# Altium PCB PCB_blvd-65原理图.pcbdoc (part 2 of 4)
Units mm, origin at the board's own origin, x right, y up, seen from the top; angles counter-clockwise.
Board outline 317.5 x 107.96 mm, 2 copper layers (Top Layer, Bottom Layer); 180 components, 111 nets, 404 pads, 231 vias.
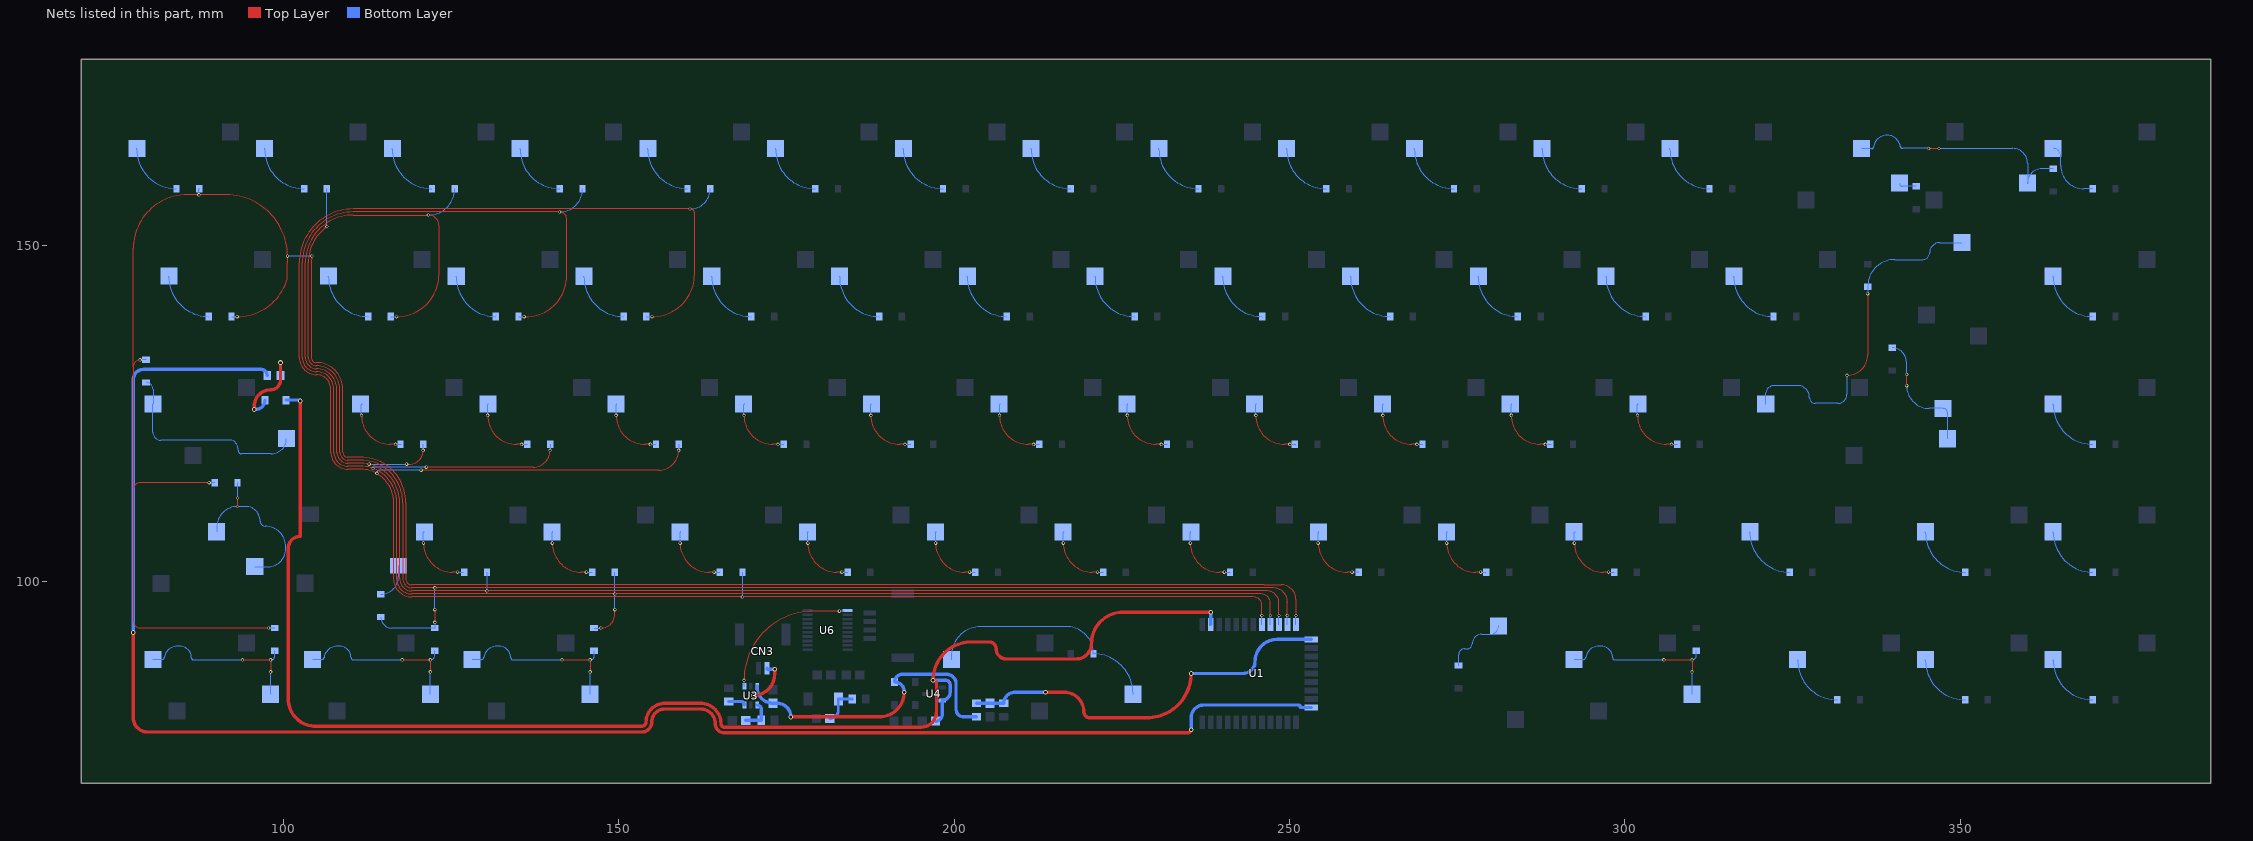
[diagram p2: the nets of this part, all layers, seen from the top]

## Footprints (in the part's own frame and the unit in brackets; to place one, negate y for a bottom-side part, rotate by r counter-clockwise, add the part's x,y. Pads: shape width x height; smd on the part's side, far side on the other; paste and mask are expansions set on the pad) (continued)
凯华轴座无灯#2 [mm]
  rect 2.54x2.54 smd far side: COL(-7.6,2.59)
  rect 2.54x2.3 smd far side: ROW(6.35,5.2)
  Multi-Layer board cut-out: -2.285,2.565 -2.49,3.31 -3.038,3.854 -3.785,4.053 -4.531,3.854 -5.079,3.31 -5.284,2.565 -5.284,2.565 -5.079,1.821 -4.531,1.277 -3.785,1.078 -3.038,1.277 -2.49,1.821 -2.285,2.565
  Multi-Layer board cut-out: 4.116,4.953 3.911,5.698 3.363,6.242 2.616,6.441 1.87,6.242 1.321,5.698 1.116,4.953 1.116,4.953 1.321,4.208 1.87,3.664 2.616,3.465 3.363,3.664 3.911,4.208 4.116,4.953
  Multi-Layer board cut-out: 2,0 1.802,0.868 1.247,1.564 0.445,1.95 -0.445,1.95 -1.247,1.564 -1.802,0.868 -2,0 -2,0 -1.802,-0.868 -1.247,-1.564 -0.445,-1.95 0.445,-1.95 1.247,-1.564 1.802,-0.868 2,0
  Multi-Layer board cut-out: -4.028,-0.025 -4.157,0.448 -4.505,0.793 -4.978,0.92 -5.452,0.793 -5.799,0.448 -5.928,-0.025 -5.928,-0.025 -5.799,-0.498 -5.452,-0.844 -4.978,-0.97 -4.505,-0.844 -4.157,-0.498 -4.028,-0.025
  Multi-Layer board cut-out: 5.979,-0.025 5.85,0.448 5.503,0.793 5.029,0.92 4.556,0.793 4.208,0.448 4.079,-0.025 4.079,-0.025 4.208,-0.498 4.556,-0.844 5.029,-0.97 5.503,-0.844 5.85,-0.498 5.979,-0.025
  Multi-Layer keep-out region: -2.285,2.565 -2.49,3.31 -3.038,3.854 -3.785,4.053 -4.531,3.854 -5.079,3.31 -5.284,2.565 -5.284,2.565 -5.079,1.821 -4.531,1.277 -3.785,1.078 -3.038,1.277 -2.49,1.821 -2.285,2.565
  Multi-Layer keep-out region: 4.116,4.953 3.911,5.698 3.363,6.242 2.616,6.441 1.87,6.242 1.321,5.698 1.116,4.953 1.116,4.953 1.321,4.208 1.87,3.664 2.616,3.465 3.363,3.664 3.911,4.208 4.116,4.953
  Multi-Layer keep-out region: 2,0 1.802,0.868 1.247,1.564 0.445,1.95 -0.445,1.95 -1.247,1.564 -1.802,0.868 -2,0 -2,0 -1.802,-0.868 -1.247,-1.564 -0.445,-1.95 0.445,-1.95 1.247,-1.564 1.802,-0.868 2,0
  Multi-Layer keep-out region: -4.028,-0.025 -4.157,0.448 -4.505,0.793 -4.978,0.92 -5.452,0.793 -5.799,0.448 -5.928,-0.025 -5.928,-0.025 -5.799,-0.498 -5.452,-0.844 -4.978,-0.97 -4.505,-0.844 -4.157,-0.498 -4.028,-0.025
  Multi-Layer keep-out region: 5.979,-0.025 5.85,0.448 5.503,0.793 5.029,0.92 4.556,0.793 4.208,0.448 4.079,-0.025 4.079,-0.025 4.208,-0.498 4.556,-0.844 5.029,-0.97 5.503,-0.844 5.85,-0.498 5.979,-0.025
凯华轴座无灯#3 [mm]
  rect 2.54x2.3 smd far side: COL(-7.6,2.47)
  rect 2.54x2.54 smd far side: ROW(6.35,5.08)
  Multi-Layer board cut-out: -5.285,2.565 -5.079,1.821 -4.531,1.278 -3.785,1.079 -3.039,1.278 -2.49,1.821 -2.285,2.565 -2.285,2.565 -2.49,3.309 -3.039,3.853 -3.785,4.052 -4.531,3.853 -5.079,3.31 -5.285,2.565
  Multi-Layer board cut-out: 1.116,4.953 1.322,4.209 1.87,3.665 2.616,3.467 3.362,3.665 3.911,4.209 4.116,4.953 4.116,4.953 3.911,5.697 3.362,6.24 2.616,6.439 1.87,6.241 1.322,5.697 1.116,4.953
  Multi-Layer board cut-out: -2,0 -1.802,-0.868 -1.247,-1.564 -0.445,-1.95 0.445,-1.95 1.247,-1.564 1.802,-0.868 2,0 2,0 1.732,1 1,1.732 0,2 -1,1.732 -1.732,1 -2,0
  Multi-Layer board cut-out: -5.928,-0.025 -5.799,-0.497 -5.451,-0.842 -4.978,-0.969 -4.505,-0.842 -4.158,-0.498 -4.028,-0.026 -4.028,-0.026 -4.158,0.447 -4.505,0.791 -4.978,0.918 -5.451,0.792 -5.799,0.447 -5.928,-0.025
  Multi-Layer board cut-out: 4.079,-0.025 4.209,-0.497 4.556,-0.842 5.029,-0.969 5.502,-0.842 5.85,-0.498 5.979,-0.026 5.979,-0.026 5.85,0.447 5.502,0.791 5.029,0.918 4.556,0.792 4.209,0.447 4.079,-0.025
  Multi-Layer keep-out region: -5.285,2.565 -5.079,1.821 -4.531,1.278 -3.785,1.079 -3.039,1.278 -2.49,1.821 -2.285,2.565 -2.285,2.565 -2.49,3.309 -3.039,3.853 -3.785,4.052 -4.531,3.853 -5.079,3.31 -5.285,2.565
  Multi-Layer keep-out region: 1.116,4.953 1.322,4.209 1.87,3.665 2.616,3.467 3.362,3.665 3.911,4.209 4.116,4.953 4.116,4.953 3.911,5.697 3.362,6.24 2.616,6.439 1.87,6.241 1.322,5.697 1.116,4.953
  Multi-Layer keep-out region: -2,0 -1.802,-0.868 -1.247,-1.564 -0.445,-1.95 0.445,-1.95 1.247,-1.564 1.802,-0.868 2,0 2,0 1.732,1 1,1.732 0,2 -1,1.732 -1.732,1 -2,0
  Multi-Layer keep-out region: -5.928,-0.025 -5.799,-0.497 -5.451,-0.842 -4.978,-0.969 -4.505,-0.842 -4.158,-0.498 -4.028,-0.026 -4.028,-0.026 -4.158,0.447 -4.505,0.791 -4.978,0.918 -5.451,0.792 -5.799,0.447 -5.928,-0.025
  Multi-Layer keep-out region: 4.079,-0.025 4.209,-0.497 4.556,-0.842 5.029,-0.969 5.502,-0.842 5.85,-0.498 5.979,-0.026 5.979,-0.026 5.85,0.447 5.502,0.791 5.029,0.918 4.556,0.792 4.209,0.447 4.079,-0.025
凯华轴座无灯#4 [mm]
  rect 2.54x2.54 smd far side: COL(-7.6,2.59) ROW(6.35,5.08)
  Multi-Layer board cut-out: -3.785,4.065 -4.435,3.917 -4.957,3.501 -5.247,2.899 -5.247,2.232 -4.957,1.63 -4.435,1.214 -3.785,1.065 -3.785,1.065 -3.134,1.214 -2.612,1.63 -2.322,2.232 -2.322,2.899 -2.612,3.501 -3.134,3.917 -3.785,4.065
  Multi-Layer board cut-out: 2.616,6.453 1.965,6.304 1.443,5.888 1.154,5.287 1.154,4.619 1.443,4.018 1.965,3.602 2.616,3.453 2.616,3.453 3.267,3.602 3.789,4.018 4.079,4.619 4.079,5.287 3.789,5.888 3.267,6.304 2.616,6.453
  Multi-Layer board cut-out: 0,2 -0.993,1.727 -1.719,0.995 -1.984,0 -1.719,-0.995 -0.993,-1.727 0,-2 0,-2 0.993,-1.727 1.719,-0.995 1.984,0 1.719,0.995 0.993,1.727 0,2
  Multi-Layer board cut-out: -4.978,0.925 -5.391,0.831 -5.721,0.567 -5.905,0.186 -5.905,-0.237 -5.721,-0.618 -5.391,-0.881 -4.978,-0.975 -4.978,-0.975 -4.503,-0.848 -4.156,-0.5 -4.028,-0.025 -4.156,0.45 -4.503,0.797 -4.978,0.925
  Multi-Layer board cut-out: 5.029,0.925 4.617,0.831 4.286,0.567 4.103,0.186 4.103,-0.237 4.286,-0.618 4.617,-0.881 5.029,-0.975 5.029,-0.975 5.504,-0.848 5.852,-0.5 5.979,-0.025 5.852,0.45 5.504,0.797 5.029,0.925
  Multi-Layer keep-out region: -3.785,4.065 -4.435,3.917 -4.957,3.501 -5.247,2.899 -5.247,2.232 -4.957,1.63 -4.435,1.214 -3.785,1.065 -3.785,1.065 -3.134,1.214 -2.612,1.63 -2.322,2.232 -2.322,2.899 -2.612,3.501 -3.134,3.917 -3.785,4.065
  Multi-Layer keep-out region: 2.616,6.453 1.965,6.304 1.443,5.888 1.154,5.287 1.154,4.619 1.443,4.018 1.965,3.602 2.616,3.453 2.616,3.453 3.267,3.602 3.789,4.018 4.079,4.619 4.079,5.287 3.789,5.888 3.267,6.304 2.616,6.453
  Multi-Layer keep-out region: 0,2 -0.993,1.727 -1.719,0.995 -1.984,0 -1.719,-0.995 -0.993,-1.727 0,-2 0,-2 0.993,-1.727 1.719,-0.995 1.984,0 1.719,0.995 0.993,1.727 0,2
  Multi-Layer keep-out region: -4.978,0.925 -5.391,0.831 -5.721,0.567 -5.905,0.186 -5.905,-0.237 -5.721,-0.618 -5.391,-0.881 -4.978,-0.975 -4.978,-0.975 -4.503,-0.848 -4.156,-0.5 -4.028,-0.025 -4.156,0.45 -4.503,0.797 -4.978,0.925
  Multi-Layer keep-out region: 5.029,0.925 4.617,0.831 4.286,0.567 4.103,0.186 4.103,-0.237 4.286,-0.618 4.617,-0.881 5.029,-0.975 5.029,-0.975 5.504,-0.848 5.852,-0.5 5.979,-0.025 5.852,0.45 5.504,0.797 5.029,0.925
卫星轴2U#1 [mm]
  Multi-Layer board cut-out: -9.987,7.703 -10.203,8.485 -10.779,9.055 -11.562,9.264 -12.346,9.055 -12.922,8.485 -13.137,7.703 -13.137,7.703 -12.922,6.922 -12.346,6.351 -11.562,6.142 -10.779,6.351 -10.203,6.922 -9.987,7.703
  Multi-Layer board cut-out: 13.812,7.703 13.597,8.485 13.021,9.055 12.237,9.264 11.454,9.055 10.878,8.485 10.662,7.703 10.662,7.703 10.878,6.922 11.454,6.351 12.237,6.142 13.021,6.351 13.597,6.922 13.812,7.703
  Multi-Layer board cut-out: -9.562,-7.636 -9.761,-6.768 -10.315,-6.072 -11.117,-5.686 -12.008,-5.686 -12.809,-6.072 -13.364,-6.768 -13.563,-7.636 -13.563,-7.636 -13.364,-8.504 -12.809,-9.2 -12.008,-9.586 -11.117,-9.586 -10.315,-9.2 -9.76,-8.504 -9.562,-7.636
  Multi-Layer board cut-out: 14.237,-7.636 14.039,-6.768 13.484,-6.072 12.682,-5.686 11.792,-5.686 10.99,-6.072 10.435,-6.768 10.237,-7.636 10.237,-7.636 10.435,-8.504 10.99,-9.2 11.792,-9.586 12.682,-9.586 13.484,-9.2 14.039,-8.504 14.237,-7.636
  Multi-Layer keep-out region: -9.987,7.703 -10.203,8.485 -10.779,9.055 -11.562,9.264 -12.346,9.055 -12.922,8.485 -13.137,7.703 -13.137,7.703 -12.922,6.922 -12.346,6.351 -11.562,6.142 -10.779,6.351 -10.203,6.922 -9.987,7.703
  Multi-Layer keep-out region: 13.812,7.703 13.597,8.485 13.021,9.055 12.237,9.264 11.454,9.055 10.878,8.485 10.662,7.703 10.662,7.703 10.878,6.922 11.454,6.351 12.237,6.142 13.021,6.351 13.597,6.922 13.812,7.703
  Multi-Layer keep-out region: -9.562,-7.636 -9.761,-6.768 -10.315,-6.072 -11.117,-5.686 -12.008,-5.686 -12.809,-6.072 -13.364,-6.768 -13.563,-7.636 -13.563,-7.636 -13.364,-8.504 -12.809,-9.2 -12.008,-9.586 -11.117,-9.586 -10.315,-9.2 -9.76,-8.504 -9.562,-7.636
  Multi-Layer keep-out region: 14.237,-7.636 14.039,-6.768 13.484,-6.072 12.682,-5.686 11.792,-5.686 10.99,-6.072 10.435,-6.768 10.237,-7.636 10.237,-7.636 10.435,-8.504 10.99,-9.2 11.792,-9.586 12.682,-9.586 13.484,-9.2 14.039,-8.504 14.237,-7.636
卫星轴2U#2 [mm]
  Multi-Layer board cut-out: -11.562,9.278 -12.246,9.122 -12.794,8.685 -13.098,8.054 -13.098,7.353 -12.794,6.721 -12.246,6.284 -11.562,6.128 -11.562,6.128 -10.879,6.284 -10.331,6.721 -10.027,7.353 -10.027,8.054 -10.331,8.685 -10.879,9.122 -11.562,9.278
  Multi-Layer board cut-out: 12.237,9.278 11.554,9.122 11.006,8.685 10.702,8.054 10.702,7.353 11.006,6.721 11.554,6.284 12.237,6.128 12.237,6.128 12.921,6.284 13.469,6.721 13.773,7.353 13.773,8.054 13.469,8.685 12.921,9.122 12.237,9.278
  Multi-Layer board cut-out: -11.562,-5.636 -12.558,-5.907 -13.286,-6.639 -13.552,-7.636 -13.286,-8.633 -12.558,-9.365 -11.562,-9.636 -11.562,-9.636 -10.567,-9.365 -9.839,-8.633 -9.572,-7.636 -9.839,-6.639 -10.567,-5.907 -11.562,-5.636
  Multi-Layer board cut-out: 12.237,-5.636 11.242,-5.907 10.514,-6.639 10.247,-7.636 10.514,-8.633 11.242,-9.365 12.237,-9.636 12.237,-9.636 13.233,-9.365 13.961,-8.633 14.227,-7.636 13.961,-6.639 13.233,-5.907 12.237,-5.636
  Multi-Layer keep-out region: -11.562,9.278 -12.246,9.122 -12.794,8.685 -13.098,8.054 -13.098,7.353 -12.794,6.721 -12.246,6.284 -11.562,6.128 -11.562,6.128 -10.879,6.284 -10.331,6.721 -10.027,7.353 -10.027,8.054 -10.331,8.685 -10.879,9.122 -11.562,9.278
  Multi-Layer keep-out region: 12.237,9.278 11.554,9.122 11.006,8.685 10.702,8.054 10.702,7.353 11.006,6.721 11.554,6.284 12.237,6.128 12.237,6.128 12.921,6.284 13.469,6.721 13.773,7.353 13.773,8.054 13.469,8.685 12.921,9.122 12.237,9.278
  Multi-Layer keep-out region: -11.562,-5.636 -12.558,-5.907 -13.286,-6.639 -13.552,-7.636 -13.286,-8.633 -12.558,-9.365 -11.562,-9.636 -11.562,-9.636 -10.567,-9.365 -9.839,-8.633 -9.572,-7.636 -9.839,-6.639 -10.567,-5.907 -11.562,-5.636
  Multi-Layer keep-out region: 12.237,-5.636 11.242,-5.907 10.514,-6.639 10.247,-7.636 10.514,-8.633 11.242,-9.365 12.237,-9.636 12.237,-9.636 13.233,-9.365 13.961,-8.633 14.227,-7.636 13.961,-6.639 13.233,-5.907 12.237,-5.636

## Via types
v1: diameter 0.5, hole 0.3, Top Layer to Bottom Layer, 198 vias
v2: diameter 0.7, hole 0.4, Top Layer to Bottom Layer, 33 vias

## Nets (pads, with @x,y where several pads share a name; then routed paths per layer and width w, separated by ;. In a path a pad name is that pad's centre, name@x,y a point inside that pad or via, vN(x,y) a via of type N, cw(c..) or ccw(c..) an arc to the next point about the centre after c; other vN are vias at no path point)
3V3: C10.2 LED1.1 U1.2 U4.2 | length 218.4
  Top Layer w0.5: v2(102.489,126.873) 102.489,106.68 ccw(c102.489,104.902) 100.711,104.902 100.711,82.423 ccw(c104.775,82.423) 104.775,78.359 153.416,78.359 ccw(c153.416,78.994) 154.051,78.994 cw(c156.845,78.994) 156.845,81.788 162.179,81.788 cw(c162.179,78.74) 165.227,78.74 ccw(c165.735,78.74) 165.735,78.232 195.072,78.232 ccw(c195.072,80.518) 197.358,80.518 197.358,84.709 ccw(c196.85,84.709) v2(196.85,85.217) cw(c202.565,85.217) 202.565,90.932 205.232,90.932 cw(c205.232,89.916) 206.248,89.916 ccw(c207.772,89.916) 207.772,88.392 218.186,88.392 ccw(c218.186,90.678) 220.472,90.678 cw(c225.171,90.678) 225.171,95.377 v2(238.252,95.377)
  Bottom Layer w0.5: LED1.1@100.386,127 102.362,127 cw(c102.362,126.873) v2(102.489,126.873) ; v2(196.85,85.217) 198.755,85.217 cw(c198.755,84.582) 199.39,84.582 199.39,83.413 cw(c198.212,83.413) U4.2@198.212,82.235 198.212,80.118 cw(c197.215,80.118) C10.2@197.215,79.121 ; v2(238.252,95.377) 238.252,93.544 ccw(c238.263,93.544) U1.2@238.263,93.533
$1N338: C6.2 R1.1 U3.4 | length 4.9
  Bottom Layer w0.5: C6.2@168.894,79.248 R1.1@171.212,79.248 171.212,80.941 ccw(c170.622,80.941) U3.4@170.622,81.531
$1N367: R2.1 U3.6 | length 2.7
  Bottom Layer w0.5: R2.1@166.37,82.058 168.195,82.058 cw(c168.195,81.531) U3.6@168.722,81.531
$1N421: C1.2 R5.2 SW2.1 | length 5.7
  Bottom Layer w0.4: C1.2@181.467,79.502 ccw(c181.467,80.752) 182.717,80.752 SW2.1@182.717,82.423 R5.2@184.801,82.423
$1N505: D10.1 KEY00.COL | length 9.4
  Bottom Layer w0.1: KEY00.COL@78.125,164.516 78.125,164.404 ccw(c84.033,164.404) D10.1@84.033,158.496
$1N744: LED1.2 R8.1 | length 13.5
  Top Layer w0.5: v2(95.631,125.603) 95.631,126.111 cw(c98.044,126.111) 98.044,128.524 ccw(c98.044,130.032) 99.552,130.032 v2(99.552,132.588)
  Bottom Layer w0.5: v2(95.631,125.603) 95.829,125.603 ccw(c95.829,127) LED1.2@97.226,127 ; R8.1@99.552,130.683 v2(99.552,132.588)
$1N1103: D1.1 KEY01.COL | length 9.4
  Bottom Layer w0.1: KEY01.COL@97.175,164.516 97.175,164.404 ccw(c103.083,164.404) D1.1@103.083,158.496
$1N1104: D2.1 KEY02.COL | length 9.4
  Bottom Layer w0.1: KEY02.COL@116.225,164.516 116.225,164.404 ccw(c122.133,164.404) D2.1@122.133,158.496
$1N1105: D3.1 KEY03.COL | length 9.4
  Bottom Layer w0.1: KEY03.COL@135.275,164.516 135.275,164.404 ccw(c141.183,164.404) D3.1@141.183,158.496
$1N1106: D4.1 KEY04.COL | length 9.4
  Bottom Layer w0.1: KEY04.COL@154.325,164.516 154.325,164.404 ccw(c160.233,164.404) D4.1@160.233,158.496
$1N1107: D5.1 KEY05.COL | length 9.4
  Bottom Layer w0.1: KEY05.COL@173.374,164.516 173.374,164.405 ccw(c179.283,164.405) D5.1@179.283,158.496
$1N1108: D6.1 KEY06.COL | length 9.4
  Bottom Layer w0.1: KEY06.COL@192.423,164.516 192.423,164.406 ccw(c198.333,164.406) D6.1@198.333,158.496
$1N1109: D7.1 KEY07.COL | length 9.4
  Bottom Layer w0.1: KEY07.COL@211.475,164.516 211.475,164.404 ccw(c217.383,164.404) D7.1@217.383,158.496
$1N1110: D8.1 KEY08.COL | length 9.4
  Bottom Layer w0.1: KEY08.COL@230.525,164.516 230.525,164.404 ccw(c236.433,164.404) D8.1@236.433,158.496
$1N1111: D9.1 KEY09.COL | length 9.4
  Bottom Layer w0.1: KEY09.COL@249.575,164.516 249.575,164.404 ccw(c255.483,164.404) D9.1@255.483,158.496
$1N1112: D11.1 KEY010.COL | length 9.4
  Bottom Layer w0.1: KEY010.COL@268.626,164.515 268.626,164.403 ccw(c274.533,164.403) D11.1@274.533,158.496
$1N1113: D12.1 KEY011.COL | length 9.4
  Bottom Layer w0.1: KEY011.COL@287.675,164.516 287.675,164.404 ccw(c293.583,164.404) D12.1@293.583,158.496
$1N1114: D13.1 KEY012.COL | length 9.4
  Bottom Layer w0.1: KEY012.COL@306.726,164.515 306.726,164.403 ccw(c312.633,164.403) D13.1@312.633,158.496
$1N1115: D14.1 KEY013.COL | length 2.8
  Bottom Layer w0.1: KEY013.COL@340.975,159.335 ccw(c341.454,159.335) 341.454,158.857 D14.1@343.463,158.857
$1N1116: D15.1 KEY014.COL KEY014_CP.COL | length 36.3
  Top Layer w0.1: v1(345.313,164.515) v1(346.837,164.515)
  Bottom Layer w0.1: KEY014_CP.COL@335.3,164.52 ccw(c335.355,164.52) 335.355,164.465 336.843,164.465 ccw(c336.843,164.694) 337.066,164.643 ; v1(345.313,164.515) 341.41,164.515 cw(c341.41,164.837) 341.104,164.736 ; v1(346.837,164.515) 357.836,164.515 cw(c357.836,162.306) 360.045,162.306 KEY014.COL@360.045,159.636 ; D15.1@363.874,161.483 362.168,161.483 ccw(c362.168,159.34) KEY014.COL@360.045,159.636 ; 337.066,164.643 ccw(c336.843,164.694) 337.072,164.694 337.072,164.7 ; 337.066,164.643 cw(c339.09,164.465) 337.072,164.7 ; 337.072,164.7 cw(c339.09,164.465) 339.09,166.497 cw(c339.09,164.465) 341.088,164.837 ; 341.088,164.837 ccw(c341.41,164.837) 341.104,164.736 ; 341.088,164.837 cw(c339.09,164.465) 341.104,164.736 ; KEY014.COL@360.045,159.636 360.045,159.361 cw(c360.025,159.361) KEY014.COL@360.025,159.34 cw(c362.168,159.34) KEY014.COL@360.045,159.636
$1N1117: D16.1 KEY015.COL | length 10
  Bottom Layer w0.1: KEY015.COL@363.875,164.516 cw(c363.875,163.393) 364.998,163.393 364.998,161.925 ccw(c368.427,161.925) 368.427,158.496 D16.1@369.783,158.496
$1N1577: D17.1 KEY115.COL | length 9.4
  Bottom Layer w0.1: KEY115.COL@363.876,145.465 363.876,145.353 ccw(c369.783,145.353) D17.1@369.783,139.446
$1N1578: D18.1 KEY114.COL KEY114_CP.COL | length 52.3
  Top Layer w0.1: v1(333.121,130.683) 333.159,130.683 ccw(c333.159,133.731) 336.207,133.731 v1(336.207,142.875)
  Bottom Layer w0.1: KEY114_CP.COL@321.013,126.415 cw(c321.013,126.498) 320.929,126.498 320.929,127.762 cw(c322.326,127.762) 322.326,129.159 325.755,129.159 cw(c325.755,127.381) 327.533,127.381 ccw(c328.422,127.381) 328.422,126.492 331.724,126.492 ccw(c331.724,127.889) 333.121,127.889 v1(333.121,130.683) ; v1(336.207,142.875) D18.1@336.207,143.881 cw(c340.281,143.881) 340.281,147.955 344.424,147.955 ccw(c344.424,148.971) 345.44,148.971 cw(c346.941,148.971) 346.941,150.472 KEY114.COL@350.255,150.472
$1N1579: D19.1 KEY113.COL | length 9.4
  Bottom Layer w0.1: KEY113.COL@316.251,145.465 316.251,145.354 ccw(c322.158,145.354) D19.1@322.158,139.446
$1N1580: D20.1 KEY112.COL | length 9.4
  Bottom Layer w0.1: KEY112.COL@297.201,145.465 297.201,145.353 ccw(c303.108,145.353) D20.1@303.108,139.446
$1N1581: D21.1 KEY111.COL | length 9.4
  Bottom Layer w0.1: KEY111.COL@278.151,145.465 278.151,145.353 ccw(c284.058,145.353) D21.1@284.058,139.446
$1N1582: D22.1 KEY110.COL | length 9.4
  Bottom Layer w0.1: KEY110.COL@259.101,145.465 259.101,145.354 ccw(c265.008,145.354) D22.1@265.008,139.446
$1N1583: D23.1 KEY19.COL | length 9.4
  Bottom Layer w0.1: KEY19.COL@240.05,145.465 240.05,145.354 ccw(c245.958,145.354) D23.1@245.958,139.446
$1N1584: D24.1 KEY18.COL | length 9.4
  Bottom Layer w0.1: KEY18.COL@221.001,145.465 221.001,145.353 ccw(c226.908,145.353) D24.1@226.908,139.446
$1N1585: D25.1 KEY17.COL | length 9.4
  Bottom Layer w0.1: KEY17.COL@201.951,145.465 201.951,145.353 ccw(c207.858,145.353) D25.1@207.858,139.446
$1N1586: D26.1 KEY16.COL | length 9.4
  Bottom Layer w0.1: KEY16.COL@182.901,145.465 182.901,145.353 ccw(c188.808,145.353) D26.1@188.808,139.446
$1N1587: D27.1 KEY15.COL | length 9.4
  Bottom Layer w0.1: KEY15.COL@163.851,145.465 163.851,145.354 ccw(c169.758,145.354) D27.1@169.758,139.446
$1N1588: D28.1 KEY14.COL | length 9.4
  Bottom Layer w0.1: KEY14.COL@144.8,145.465 144.8,145.354 ccw(c150.708,145.354) D28.1@150.708,139.446
$1N1589: D29.1 KEY13.COL | length 9.4
  Bottom Layer w0.1: KEY13.COL@125.751,145.465 125.751,145.354 ccw(c131.658,145.354) D29.1@131.658,139.446
$1N1590: D30.1 KEY12.COL | length 9.4
  Bottom Layer w0.1: KEY12.COL@106.7,145.466 106.7,145.354 ccw(c112.608,145.354) D30.1@112.608,139.446
$1N1891: D32.1 KEY10.COL | length 9.4
  Bottom Layer w0.1: KEY10.COL@82.888,145.466 82.888,145.417 ccw(c88.859,145.417) D32.1@88.859,139.446
$1N2119: D33.1 KEY215.COL | length 9.4
  Bottom Layer w0.1: KEY215.COL@363.876,126.415 363.876,126.303 ccw(c369.783,126.303) D33.1@369.783,120.396
$1N2120: D35.1 KEY213.COL KEY213_CP.COL | length 19.1
  Top Layer w0.1: v1(342.011,129.159) v1(342.011,130.81)
  Bottom Layer w0.1: D35.1@339.852,134.789 cw(c339.852,132.63) 342.011,132.63 v1(342.011,130.81) ; v1(342.011,129.159) ccw(c345.423,129.159) 345.423,125.748 KEY213_CP.COL@347.454,125.748 cw(c347.454,125.083) 348.119,125.083 KEY213.COL@348.119,121.232
$1N2121: D36.1 KEY212.COL | length 10.1
  Top Layer w0.1: v1(301.879,124.714) ccw(c306.197,124.714) 306.197,120.396 v1(306.959,120.396)
  Bottom Layer w0.1: v1(301.879,124.714) 301.879,126.321 cw(c301.963,126.321) KEY212.COL@301.963,126.405 ; v1(306.959,120.396) D36.1@307.807,120.396
$1N2122: D37.1 KEY211.COL | length 10.1
  Top Layer w0.1: v1(283.073,124.714) ccw(c287.391,124.714) 287.391,120.396 v1(288.153,120.396)
  Bottom Layer w0.1: v1(283.073,124.714) 283.073,126.321 cw(c283.157,126.321) KEY211.COL@283.157,126.405 ; v1(288.153,120.396) D37.1@289.001,120.396
$1N2123: D38.1 KEY210.COL | length 10.1
  Top Layer w0.1: v1(263.906,124.714) ccw(c268.224,124.714) 268.224,120.396 v1(268.986,120.396)
  Bottom Layer w0.1: v1(263.906,124.714) 263.906,126.321 cw(c263.99,126.321) KEY210.COL@263.99,126.405 ; v1(268.986,120.396) D38.1@269.834,120.396
$1N2124: D39.1 KEY29.COL | length 10.1
  Top Layer w0.1: v1(244.973,124.714) ccw(c249.291,124.714) 249.291,120.396 v1(250.053,120.396)
  Bottom Layer w0.1: v1(244.973,124.714) 244.973,126.321 cw(c245.057,126.321) KEY29.COL@245.057,126.405 ; v1(250.053,120.396) D39.1@250.901,120.396
$1N2125: D40.1 KEY28.COL | length 10.1
  Top Layer w0.1: v1(225.806,124.714) ccw(c230.124,124.714) 230.124,120.396 v1(230.886,120.396)
  Bottom Layer w0.1: v1(225.806,124.714) 225.806,126.321 cw(c225.89,126.321) KEY28.COL@225.89,126.405 ; v1(230.886,120.396) D40.1@231.734,120.396
$1N2126: D41.1 KEY27.COL | length 10.1
  Top Layer w0.1: v1(206.756,124.714) ccw(c211.074,124.714) 211.074,120.396 v1(211.836,120.396)
  Bottom Layer w0.1: v1(206.756,124.714) 206.756,126.321 cw(c206.84,126.321) KEY27.COL@206.84,126.405 ; v1(211.836,120.396) D41.1@212.684,120.396
$1N2127: D42.1 KEY26.COL | length 10.1
  Top Layer w0.1: v1(187.579,124.714) ccw(c191.897,124.714) 191.897,120.396 v1(192.659,120.396)
  Bottom Layer w0.1: v1(187.579,124.714) 187.579,126.321 cw(c187.663,126.321) KEY26.COL@187.663,126.405 ; v1(192.659,120.396) D42.1@193.507,120.396
$1N2128: D43.1 KEY25.COL | length 10.1
  Top Layer w0.1: v1(168.656,124.714) ccw(c172.974,124.714) 172.974,120.396 v1(173.736,120.396)
  Bottom Layer w0.1: v1(168.656,124.714) 168.656,126.321 cw(c168.74,126.321) KEY25.COL@168.74,126.405 ; v1(173.736,120.396) D43.1@174.584,120.396
$1N2129: D44.1 KEY24.COL | length 10.1
  Top Layer w0.1: v1(149.606,124.714) ccw(c153.924,124.714) 153.924,120.396 v1(154.686,120.396)
  Bottom Layer w0.1: v1(149.606,124.714) 149.606,126.321 cw(c149.69,126.321) KEY24.COL@149.69,126.405 ; v1(154.686,120.396) D44.1@155.534,120.396
$1N2130: D45.1 KEY23.COL | length 10.1
  Top Layer w0.1: v1(130.429,124.714) ccw(c134.747,124.714) 134.747,120.396 v1(135.509,120.396)
  Bottom Layer w0.1: v1(130.429,124.714) 130.429,126.321 cw(c130.513,126.321) KEY23.COL@130.513,126.405 ; v1(135.509,120.396) D45.1@136.357,120.396
$1N2131: D46.1 KEY22.COL | length 10.1
  Top Layer w0.1: v1(111.623,124.714) ccw(c115.941,124.714) 115.941,120.396 v1(116.703,120.396)
  Bottom Layer w0.1: v1(111.623,124.714) 111.623,126.321 cw(c111.707,126.321) KEY22.COL@111.707,126.405 ; v1(116.703,120.396) D46.1@117.551,120.396
$1N2412: D48.1 KEY20.COL KEY20_CP.COL | length 31.2
  Bottom Layer w0.1: D48.1@79.502,129.626 cw(c79.502,128.589) 80.539,128.589 KEY20_CP.COL@80.539,126.415 ccw(c80.539,126.395) 80.518,126.395 80.518,122.174 ccw(c81.661,122.174) 81.661,121.031 91.948,121.031 cw(c91.948,119.761) 93.218,119.761 93.218,119.507 ccw(c93.726,119.507) 93.726,118.999 98.201,118.999 ccw(c98.201,121.235) KEY20.COL@100.437,121.235
$1N2656: D49.1 KEY315.COL | length 9.4
  Bottom Layer w0.1: KEY315.COL@363.876,107.365 363.876,107.253 ccw(c369.783,107.253) D49.1@369.783,101.346
$1N2657: D50.1 KEY314.COL | length 9.4
  Bottom Layer w0.1: KEY314.COL@344.826,107.365 344.826,107.253 ccw(c350.733,107.253) D50.1@350.733,101.346
$1N2658: D51.1 KEY313.COL | length 9.4
  Bottom Layer w0.1: KEY313.COL@318.632,107.365 318.632,107.285 ccw(c324.571,107.285) D51.1@324.571,101.346
$1N2659: D53.1 KEY311.COL | length 10.1
  Top Layer w0.1: v1(292.481,105.664) ccw(c296.799,105.664) 296.799,101.346 v1(297.561,101.346)
  Bottom Layer w0.1: v1(292.481,105.664) 292.481,107.271 cw(c292.565,107.271) KEY311.COL@292.565,107.355 ; v1(297.561,101.346) D53.1@298.409,101.346
$1N2660: D54.1 KEY310.COL | length 10.1
  Top Layer w0.1: v1(273.431,105.664) ccw(c277.749,105.664) 277.749,101.346 v1(278.511,101.346)
  Bottom Layer w0.1: v1(273.431,105.664) 273.431,107.271 cw(c273.515,107.271) KEY310.COL@273.515,107.355 ; v1(278.511,101.346) D54.1@279.359,101.346
$1N2661: D55.1 KEY39.COL | length 10.2
  Top Layer w0.1: v1(254.264,105.664) ccw(c258.582,105.664) 258.582,101.346 v1(259.344,101.346)
  Bottom Layer w0.1: v1(254.264,105.664) 254.264,107.286 cw(c254.333,107.286) KEY39.COL@254.333,107.355 ; v1(259.344,101.346) D55.1@260.309,101.346
$1N2662: D56.1 KEY38.COL | length 10.1
  Top Layer w0.1: v1(235.204,105.664) ccw(c239.522,105.664) 239.522,101.346 v1(240.284,101.346)
  Bottom Layer w0.1: v1(235.204,105.664) 235.204,107.271 cw(c235.288,107.271) KEY38.COL@235.288,107.355 ; v1(240.284,101.346) D56.1@241.132,101.346
$1N2663: D57.1 KEY37.COL | length 10.1
  Top Layer w0.1: v1(216.281,105.664) ccw(c220.599,105.664) 220.599,101.346 v1(221.361,101.346)
  Bottom Layer w0.1: v1(216.281,105.664) 216.281,107.271 cw(c216.365,107.271) KEY37.COL@216.365,107.355 ; v1(221.361,101.346) D57.1@222.209,101.346
$1N2664: D58.1 KEY36.COL | length 10.1
  Top Layer w0.1: v1(197.226,105.664) ccw(c201.544,105.664) 201.544,101.346 v1(202.306,101.346)
  Bottom Layer w0.1: v1(197.226,105.664) 197.226,107.271 cw(c197.31,107.271) KEY36.COL@197.31,107.355 ; v1(202.306,101.346) D58.1@203.154,101.346
$1N2665: D59.1 KEY35.COL | length 10.1
  Top Layer w0.1: v1(178.176,105.664) ccw(c182.494,105.664) 182.494,101.346 v1(183.256,101.346)
  Bottom Layer w0.1: v1(178.176,105.664) 178.176,107.271 cw(c178.26,107.271) KEY35.COL@178.26,107.355 ; v1(183.256,101.346) D59.1@184.104,101.346
$1N2666: D60.1 KEY34.COL | length 10.1
  Top Layer w0.1: v1(159.126,105.664) ccw(c163.444,105.664) 163.444,101.346 v1(164.206,101.346)
  Bottom Layer w0.1: v1(159.126,105.664) 159.126,107.271 cw(c159.21,107.271) KEY34.COL@159.21,107.355 ; v1(164.206,101.346) D60.1@165.054,101.346
$1N2667: D61.1 KEY33.COL | length 10.1
  Top Layer w0.1: v1(140.076,105.664) ccw(c144.394,105.664) 144.394,101.346 v1(145.156,101.346)
  Bottom Layer w0.1: v1(140.076,105.664) 140.076,107.271 cw(c140.16,107.271) KEY33.COL@140.16,107.355 ; v1(145.156,101.346) D61.1@146.004,101.346
$1N2668: D62.1 KEY32.COL | length 10.1
  Top Layer w0.1: v1(120.868,105.664) ccw(c125.186,105.664) 125.186,101.346 v1(125.948,101.346)
  Bottom Layer w0.1: v1(120.868,105.664) 120.868,107.271 cw(c120.952,107.271) KEY32.COL@120.952,107.355 ; v1(125.948,101.346) D62.1@126.796,101.346
$1N2669: D63.1 KEY31.COL | length 5.8
  Bottom Layer w0.1: D63.1@114.497,98.037 ccw(c114.497,100.673) 117.132,100.673 KEY31.COL@117.132,102.295
$1N2970: D64.1 KEY30.COL KEY30_CP.COL | length 26.2
  Top Layer w0.1: v1(93.133,111.125) v1(93.133,112.395)
  Bottom Layer w0.1: KEY30.COL@90.032,107.366 90.032,108.024 cw(c93.133,108.024) v1(93.133,111.125) 94.361,111.125 cw(c94.361,108.966) 96.52,108.966 ccw(c97.282,108.966) 97.282,108.204 cw(c97.282,105.156) 100.33,105.156 100.33,104.775 cw(c97.71,104.775) 97.71,102.155 KEY30_CP.COL@95.706,102.155 ; v1(93.133,112.395) D64.1@93.133,114.681
$1N3118: D65.1 KEY415.COL | length 9.4
  Bottom Layer w0.1: KEY415.COL@363.876,88.315 363.876,88.203 ccw(c369.783,88.203) D65.1@369.783,82.296
$1N3119: D66.1 KEY414.COL | length 9.4
  Bottom Layer w0.1: KEY414.COL@344.826,88.315 344.826,88.203 ccw(c350.733,88.203) D66.1@350.733,82.296
$1N3120: D67.1 KEY413.COL | length 9.4
  Bottom Layer w0.1: KEY413.COL@325.776,88.315 325.776,88.203 ccw(c331.683,88.203) D67.1@331.683,82.296
$1N3121: D69.1 KEY411.COL KEY411_CP.COL | length 26.7
  Top Layer w0.1: v1(305.816,88.265) 310.007,88.265 cw(c310.007,88.256) v1(310.017,88.256) v1(310.017,86.487)
  Bottom Layer w0.1: KEY411.COL@292.437,88.316 293.82,88.316 ccw(c293.82,88.66) 294.149,88.559 ; v1@305.818,88.265 298.433,88.265 cw(c298.534,88.594) 298.19,88.594 ccw(c296.487,88.594) 296.487,90.297 296.115,90.297 ccw(c296.115,88.316) 294.164,88.66 ; KEY411_CP.COL@310.017,83.136 v1(310.017,86.487) ; v1(310.017,88.256) ccw(c310.017,88.881) 310.642,88.881 D69.1@310.642,89.621 ; 294.149,88.559 cw(c296.115,88.316) 294.164,88.66 ; 294.149,88.559 ccw(c293.82,88.66) 294.164,88.66
$1N3122: D70.1 KEY410.COL | length 10
  Bottom Layer w0.1: D70.1@275.209,87.418 275.209,89.027 cw(c276.098,89.027) 276.098,89.916 276.479,89.916 ccw(c276.479,90.678) 277.241,90.678 cw(c278.638,90.678) 278.638,92.075 279.945,92.075 ccw(c279.945,93.326) KEY410.COL@281.196,93.326
$1N3123: D74.1 KEY46.COL KEY46_CP.COL | length 35.9
  Bottom Layer w0.1: KEY46.COL@199.568,88.316 199.568,88.823 cw(c203.962,88.823) 203.962,93.218 216.704,93.218 cw(c216.704,89.154) D74.1@220.768,89.154 cw(c220.768,83.247) 226.675,83.247 KEY46_CP.COL@226.675,83.136
$1N3124: D77.1 KEY43.COL KEY43_CP.COL | length 26.7
  Top Layer w0.1: v1(141.512,88.265) 145.703,88.265 cw(c145.703,88.256) v1(145.712,88.256) v1(145.712,86.487)
  Bottom Layer w0.1: KEY43.COL@128.132,88.316 129.514,88.316 ccw(c129.514,88.66) 129.843,88.559 ; v1(141.512,88.265) 134.127,88.265 cw(c134.228,88.594) 133.884,88.594 ccw(c132.181,88.594) 132.181,90.297 131.809,90.297 ccw(c131.809,88.316) 129.858,88.66 ; KEY43_CP.COL@145.712,83.136 v1(145.712,86.487) ; v1(145.712,88.256) ccw(c145.712,88.881) 146.338,88.881 D77.1@146.338,89.621 ; 129.843,88.559 cw(c131.809,88.316) 129.858,88.66 ; 129.843,88.559 ccw(c129.514,88.66) 129.858,88.66
$1N3125: D79.1 KEY41.COL KEY41_CP.COL | length 26.7
  Top Layer w0.1: v1(117.699,88.265) 121.89,88.265 cw(c121.89,88.256) v1(121.9,88.256) v1(121.9,86.487)
  Bottom Layer w0.1: KEY41.COL@104.318,88.316 105.7,88.316 ccw(c105.7,88.66) 106.029,88.559 ; v1(117.699,88.265) 110.313,88.265 cw(c110.414,88.594) 110.07,88.594 ccw(c108.367,88.594) 108.367,90.297 107.995,90.297 ccw(c107.995,88.316) 106.044,88.66 ; KEY41_CP.COL@121.9,83.136 v1(121.9,86.487) ; v1(121.9,88.256) ccw(c121.9,88.881) 122.525,88.881 D79.1@122.525,89.621 ; 106.029,88.559 cw(c107.995,88.316) 106.044,88.66 ; 106.029,88.559 ccw(c105.7,88.66) 106.044,88.66
$1N3306: D80.1 KEY40.COL KEY40_CP.COL | length 26.7
  Top Layer w0.1: v1(93.887,88.265) 98.078,88.265 cw(c98.078,88.256) v1(98.087,88.256) v1(98.087,86.487)
  Bottom Layer w0.1: KEY40.COL@80.507,88.316 81.889,88.316 ccw(c81.889,88.66) 82.218,88.559 ; v1(93.887,88.265) 86.502,88.265 cw(c86.603,88.594) 86.259,88.594 ccw(c84.556,88.594) 84.556,90.297 84.184,90.297 ccw(c84.184,88.316) 82.233,88.66 ; KEY40_CP.COL@98.087,83.136 v1(98.087,86.487) ; v1(98.087,88.256) ccw(c98.087,88.881) 98.713,88.881 D80.1@98.713,89.621 ; 82.218,88.559 ccw(c81.889,88.66) 82.233,88.66 ; 82.218,88.559 cw(c84.184,88.316) 82.233,88.66
ADC1: C8.1 R3.1 R4.1 U1.13 | length 59.7
  Top Layer w0.5: v2(213.614,83.439) 216.408,83.439 cw(c216.408,80.518) 219.329,80.518 ccw(c220.218,80.518) 220.218,79.629 228.727,79.629 ccw(c228.727,86.233) v2(235.331,86.233)
  Bottom Layer w0.5: R3.1@203.327,81.772 C8.1@205.359,81.772 R4.1@207.391,81.772 cw(c209.058,81.772) 209.058,83.439 v2(213.614,83.439) ; v2(235.331,86.233) 243.078,86.233 ccw(c243.078,88.011) 244.856,88.011 cw(c248.158,88.011) 248.158,91.313 U1.13@253.227,91.313
BATT: C7.2 CN3.2 D101.2 R3.2 U3.3 | length 55
  Top Layer w0.5: v2(170.053,82.96) ccw(c170.053,86.135) 173.228,86.135 v2(173.228,86.868) ; v2(175.641,79.756) 188.849,79.756 ccw(c188.849,83.439) v2(192.532,83.439)
  Bottom Layer w0.5: v2(170.053,82.96) 170.949,82.96 ; U3.3@170.622,84.331 170.622,84.156 ccw(c172.974,84.156) 170.949,82.96 ; CN3.2@172.081,87.027 ccw(c172.241,87.027) 172.241,86.868 v2(173.228,86.868) ; v2(175.641,79.756) ccw(c173.593,79.756) 173.593,81.804 C7.2@172.974,81.804 cw(c172.974,84.156) 170.949,82.96 ; v2(192.532,83.439) 192.532,83.54 ccw(c191.109,83.54) D101.2@191.109,84.963 cw(c192.252,84.963) 192.252,86.106 198.882,86.106 cw(c198.882,84.709) 200.279,84.709 200.279,80.899 ccw(c201.406,80.899) 201.406,79.772 R3.2@203.327,79.772
CAPS_LOCK: R8.2 U1.21 | length 255.9
  Top Layer w0.5: v2(77.597,92.329) 77.597,79.629 ccw(c79.717,79.629) 79.717,77.509 153.416,77.509 ccw(c153.416,78.994) 154.901,78.994 cw(c156.845,78.994) 156.845,80.938 162.179,80.938 cw(c162.179,78.74) 164.377,78.74 ccw(c165.735,78.74) 165.735,77.382 234.862,77.382 ccw(c234.862,77.851) v2(235.331,77.851)
  Bottom Layer w0.5: v2(77.597,92.329) 77.597,130.048 cw(c79.121,130.048) 79.121,131.572 96.663,131.572 cw(c96.663,130.683) R8.2@97.552,130.683 ; v2(235.331,77.851) 235.331,79.629 cw(c237.236,79.629) 237.236,81.534 251.333,81.534 cw(c251.333,81.28) 251.587,81.28 ccw(c251.715,81.28) 251.715,81.153 U1.21@253.227,81.153
CHRG: U3.1 U6.11 | length 21.7
  Top Layer w0.1: v1(168.656,85.217) cw(c178.955,85.217) 178.955,95.516 v1(182.872,95.516)
  Bottom Layer w0.1: v1(168.656,85.217) 168.656,84.397 ccw(c168.722,84.397) U3.1@168.722,84.331 ; v1(182.872,95.516) U6.11@183.507,95.516
COL0: D10.2 D32.2 D48.2 D64.2 D80.2 U1.12 | length 339.2
  Top Layer w0.1: v1(78.613,133.011) ccw(c78.613,131.995) 77.597,131.995 ; 85.598,157.607 ccw(c85.598,149.606) 77.597,149.606 77.597,131.995 ; v1(88.9,114.681) 78.613,114.681 ccw(c78.613,113.665) 77.597,113.665 ; v1(97.79,93.006) 78.699,93.006 cw(c78.699,94.107) 77.597,94.107 77.597,113.665 ; 246.264,99.441 248.793,99.441 cw(c248.793,97.271) 250.963,97.271 v1(250.963,94.869) ; 77.597,113.665 77.597,131.995
  Top Layer w0.102: 85.598,157.607 v1(87.376,157.607) 91.44,157.607 cw(c91.44,148.463) v1(100.584,148.463) ; v1(93.091,139.446) ccw(c93.091,147.193) 100.536,145.052 100.536,147.447 cw(c110.385,147.447) v1@100.589,148.463 ; v1(104.226,148.476) ccw(c110.385,147.447) 104.14,147.451 104.14,133.35 ccw(c104.902,133.35) 104.902,132.588 cw(c104.902,128.651) 108.839,128.651 108.839,119.253 ccw(c109.601,119.253) 109.601,118.491 111.506,118.491 cw(c111.506,111.76) 118.237,111.76 118.237,100.33 ccw(c119.126,100.33) 119.126,99.441 246.264,99.441
  Bottom Layer w0.1: v1(78.613,133.011) D48.2@79.502,133.011 ; v1(87.376,157.607) 87.376,158.455 cw(c87.418,158.455) D10.2@87.418,158.496 ; v1(88.9,114.681) D64.2@89.748,114.681 ; v1(97.79,93.006) D80.2@98.679,93.006 ; U1.12@250.963,93.533 v1(250.963,94.869)
  Bottom Layer w0.102: D32.2@92.244,139.446 v1(93.091,139.446) ; v1(100.584,148.463) 104.14,148.463 104.213,148.463 ccw(c104.213,148.476) v1(104.226,148.476)
COL1: D1.2 D63.2 D79.2 U1.11 | length 270.8
  Top Layer w0.1: 245.446,98.989 247.605,98.989 cw(c247.605,96.901) 249.693,96.901 ccw(c249.72,96.874) 249.682,96.874 v1(249.682,94.869)
  Top Layer w0.102: v1(122.555,93.853) v1(122.555,95.758) ; 245.446,98.989 v1(122.549,98.989) 119.126,98.989 cw(c119.126,100.259) 119.118,98.989 cw(c119.126,100.33) 117.785,100.33 117.785,111.704 ccw(c111.379,111.704) 115.708,116.426 ccw(c111.506,111.76) 111.506,118.039 109.601,118.039 cw(c109.601,119.253) 108.387,119.253 108.387,128.651 ccw(c103.689,128.652) 108.387,128.657 ccw(c104.902,128.651) 104.902,132.136 cw(c104.902,133.35) 103.688,133.35 103.688,147.447 ; 103.688,147.447 cw(c110.385,147.447) v1(106.468,152.879) ; 103.688,147.447 cw(c110.385,147.447) v1(106.468,152.879) ; 103.688,147.447 cw(c110.385,147.447) v1(106.468,152.879) ; 103.688,147.447 cw(c110.385,147.447) v1(106.468,152.879) ; 103.688,147.447 cw(c110.385,147.447) v1(106.468,152.879) ; 103.688,147.447 cw(c110.385,147.447) v1(106.468,152.879) ; 103.688,147.447 cw(c110.385,147.447) v1(106.468,152.879) ; 103.688,147.447 cw(c110.385,147.447) v1(106.468,152.879) ; 103.688,147.447 cw(c110.385,147.447) v1(106.468,152.879)
  Bottom Layer w0.1: v1(249.682,94.869) cw(c249.655,94.842) 249.693,94.842 U1.11@249.693,93.533
  Bottom Layer w0.102: v1(106.468,152.879) D1.2@106.468,158.496 ; D63.2@114.497,94.652 ccw(c116.143,94.652) 116.143,93.006 D79.2@122.555,93.006 v1(122.555,93.853) ; v1(122.549,98.989) 122.555,98.983 v1(122.555,95.758)
  other v1: 106.468,152.879 106.468,152.879
COL2: D2.2 D30.2 D46.2 D62.2 U1.10 | length 260
  Top Layer w0.1: 107.936,128.655 cw(c103.238,128.65) 107.936,128.651 107.936,119.253 ccw(c109.601,119.253) 109.601,117.588 111.506,117.588 cw(c111.506,111.76) v1(112.753,117.453) cw(c111.506,111.76) 113.498,117.237 cw(c111.506,111.76) 115.405,116.092 cw(c111.379,111.704) 117.334,111.708 117.334,100.33 ; 107.936,128.656 ccw(c104.902,128.651) 104.902,131.685 cw(c104.902,133.35) 103.237,133.35 103.237,147.447 cw(c110.385,147.447) 110.385,154.595 v1(121.584,154.595) cw(c121.584,152.989) 123.19,152.989 123.19,145.796 cw(c116.84,145.796) v1(116.84,139.446) ; v1(118.364,117.439) 118.751,117.439 ccw(c118.751,119.507) v1(120.819,119.507) ; v1(248.423,94.869) 248.423,96.774 ccw(c246.659,96.774) 246.659,98.538 v1(130.324,98.538) 119.126,98.538 ; 117.334,100.33 ccw(c119.126,100.33) 119.116,98.538 ; 117.334,100.33 ccw(c119.126,100.33) 119.116,98.538 ; 117.334,100.33 ccw(c119.126,100.33) 119.116,98.538 ; 119.116,98.538 ccw(c119.126,100.316) 119.126,98.538 ; 119.116,98.538 ccw(c119.126,100.316) 119.126,98.538 ; 119.116,98.538 ccw(c119.126,100.316) 119.126,98.538
  Bottom Layer w0.1: v1(112.753,117.453) 118.35,117.453 cw(c118.35,117.439) v1(118.364,117.439) ; D30.2@115.993,139.446 v1(116.84,139.446) ; v1(120.819,119.507) D46.2@120.819,120.396 ; v1(121.584,154.595) 121.617,154.595 ccw(c121.617,158.496) D2.2@125.518,158.496 ; v1(130.324,98.538) ccw(c130.324,98.553) 130.339,98.553 D62.2@130.339,101.346 ; U1.10@248.423,93.533 v1(248.423,94.869)
COL3: D3.2 D29.2 D45.2 D61.2 D77.2 U1.9 | length 299.8
  Top Layer w0.1: v1(121.285,116.989) 137.224,116.989 ccw(c137.224,119.507) v1(139.742,119.507) ; v1(135.89,139.446) 136.144,139.446 ccw(c136.144,145.542) 142.24,145.542 142.24,153.966 ccw(c141.161,153.966) v1(141.161,155.045) 110.385,155.045 ccw(c110.385,147.447) 102.787,147.447 102.787,133.35 ccw(c104.902,133.35) 104.902,131.235 cw(c104.902,128.651) 107.486,128.656 cw(c102.784,128.651) 107.486,128.651 107.486,119.253 ccw(c109.601,119.253) 109.601,117.138 111.506,117.138 cw(c111.506,111.76) v1(113.344,116.815) cw(c111.506,111.76) 114.127,116.456 cw(c111.506,111.76) 115.102,115.759 cw(c111.379,111.704) 116.84,112.4 116.84,100.374 ccw(c119.126,100.374) 119.126,98.088 v1(149.396,98.088) 245.712,98.088 cw(c245.712,96.647) 247.153,96.647 v1(247.153,94.869) ; v1(147.32,93.006) ccw(c147.32,95.082) 149.396,95.082 v1(149.396,95.758)
  Bottom Layer w0.1: v1(113.344,116.815) cw(c113.519,116.815) 113.519,116.989 v1(121.285,116.989) ; D29.2@135.043,139.446 v1(135.89,139.446) ; v1(139.742,119.507) D45.2@139.742,120.396 ; v1(141.161,155.045) ccw(c141.161,158.452) 144.568,158.452 D3.2@144.568,158.496 ; D77.2@146.304,93.006 v1(147.32,93.006) ; D61.2@149.389,101.346 cw(c149.389,101.339) 149.396,101.339 v1(149.396,98.088) v1(149.396,95.758) ; U1.9@247.153,93.533 v1(247.153,94.869)
COL4: D4.2 D28.2 D44.2 D60.2 U1.8 | length 330.7
  Top Layer w0.1: v1(120.523,116.539) 155.951,116.539 ccw(c155.951,119.507) v1(158.919,119.507) ; v1(154.94,139.446) ccw(c154.94,145.796) 161.29,145.796 161.29,154.819 ccw(c160.614,154.819) v1(160.614,155.495) 110.385,155.495 ccw(c110.385,147.447) 102.337,147.447 102.337,133.35 ccw(c104.902,133.35) 104.902,130.785 cw(c104.902,128.651) 107.036,128.655 cw(c102.34,128.65) 107.036,128.651 107.036,119.253 ccw(c109.601,119.253) 109.601,116.688 111.506,116.688 cw(c111.506,111.76) 113.19,116.392 cw(c111.506,111.76) 113.571,116.235 cw(c111.506,111.76) v1(113.908,116.063) cw(c111.506,111.76) 114.8,115.426 cw(c111.379,111.704) 116.39,112.371 116.39,100.374 ccw(c119.126,100.374) 119.126,97.638 v1(168.423,97.638) 244.627,97.638 cw(c244.627,96.382) 245.883,96.382 v1(245.883,94.869)
  Bottom Layer w0.1: v1(113.908,116.063) 113.908,116.147 cw(c114.3,116.147) 114.3,116.539 v1(120.523,116.539) ; D28.2@154.093,139.446 v1(154.94,139.446) ; v1(158.919,119.507) D44.2@158.919,120.396 ; v1(160.614,155.495) 160.617,155.495 ccw(c160.617,158.496) D4.2@163.618,158.496 ; v1(168.423,97.638) ccw(c168.423,97.654) 168.439,97.654 D60.2@168.439,101.346 ; U1.8@245.883,93.533 v1(245.883,94.869)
